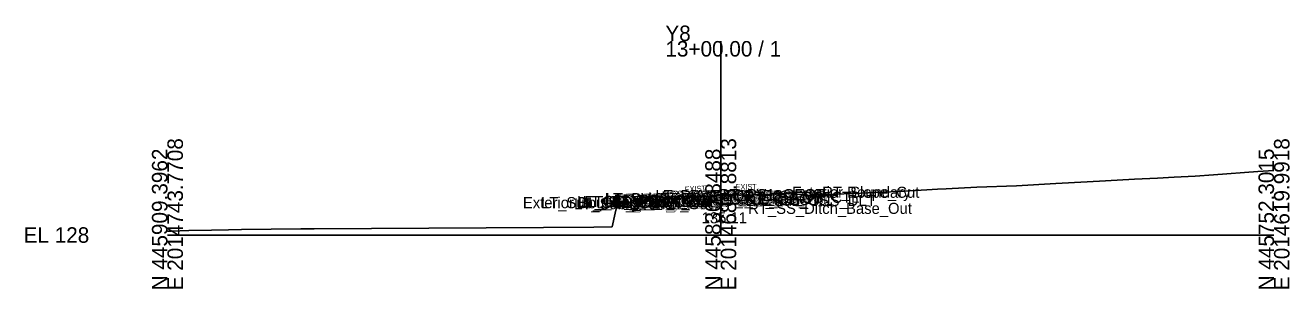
# Model space of a CAD drawing. Extents: x -26 to 1403, y -10 to 8043.
# Drawn here: x -25.7 to 202.8, y 5990.3 to 6037.9 of the extents above; entities that cross this region are included whole.
import ezdxf

# ---------------------------------------------------------------- set-up
doc = ezdxf.new("R2010")
doc.units = 0
for name, color, linetype in [('Default', 7, 'Continuous'), ('Exist Cross Section Cell', 7, 'Continuous'), ('Exist XS Center Line Elevation Label', 7, 'Continuous'), ('Exist XS Ground Line', 7, 'Continuous'), ('Prop CMT Shld Paved Course 1', 7, 'Continuous'), ('Prop XS SE Text', 7, 'Continuous'), ('Scratch_Level_0', 7, 'Continuous')]:
    doc.layers.add(name, color=color, linetype=linetype)

msp = doc.modelspace()

# ---------------------------------------------------------------- linework, layer by layer
at = {"layer": 'Exist Cross Section Cell'}
for p, q in [((100, 6000), (100, 6035.02)), ((0, 6000), (100, 6000)), ((100, 6000), (200, 6000))]:
    msp.add_line(p, q, dxfattribs=at)
at = {"layer": 'Exist XS Ground Line'}
msp.add_lwpolyline([(0, 6000.71), (0.68, 6000.72), (3.89, 6000.82), (7.97, 6000.89), (11.02, 6000.92), (13.41, 6000.98), (24.13, 6001.1), (25.26, 6001.11), (26.52, 6001.12), (67.99, 6001.36), (77.04, 6001.44), (80.37, 6001.49), (80.93, 6003.93), (81.37, 6005.77), (84.19, 6006), (85.79, 6006.13), (90.69, 6006.51), (96.04, 6006.83), (100, 6007.11), (100.96, 6007.18), (102.69, 6007.21), (108.94, 6007.31), (109.07, 6007.42), (111.89, 6007.46), (113.23, 6007.66), (115.29, 6007.66), (115.71, 6007.16), (116.35, 6007.2), (117.3, 6007.25), (123.96, 6007.52), (132.08, 6007.87), (137.25, 6008.14), (139.2, 6008.25), (140.74, 6008.32), (146.32, 6008.61), (153.47, 6008.89), (160.57, 6009.3), (166.21, 6009.61), (169.57, 6009.78), (174.81, 6010.06), (178.94, 6010.28), (181.93, 6010.44), (185.73, 6010.61), (189.05, 6010.84), (197.08, 6011.46), (200, 6011.67)], dxfattribs=at)
at = {"layer": 'Prop CMT Shld Paved Course 1'}
for points in [[(90.69, 6006.55), (90.69, 6006.55)], [(108.94, 6007.29), (108.94, 6007.29)]]:
    msp.add_lwpolyline(points, dxfattribs=at)

# ---------------------------------------------------------------- texts
at = {"layer": 'Default'}
msp.add_text('-', height=0.0001, dxfattribs=at).set_placement((0, 6000))
at = {"layer": 'Exist Cross Section Cell'}
for s, p in [('Y8', (90, 6035.02)), ('13+00.00 / 1', (90, 6032.22)), ('EL 128', (-26, 5998.6))]:
    msp.add_text(s, height=2.8, dxfattribs=at).set_placement(p)
for s, p in [('E 2014743.7708', (2.8, 5990)), ('E 2014681.8813', (102.8, 5990)), ('E 2014619.9918', (202.8, 5990)), ('N 445909.3962', (0, 5990)), ('N 445830.8488', (100, 5990)), ('N 445752.3015', (200, 5990))]:
    msp.add_text(s, height=2.8, rotation=90, dxfattribs=at).set_placement(p)
at = {"layer": 'Exist XS Center Line Elevation Label'}
msp.add_text('135.11', height=2, dxfattribs=at).set_placement((96.56, 6002.11))
at = {"layer": 'Prop XS SE Text'}
for rotation, p in [(3.4336, (93.52, 6007.72)), (1.1458, (102.68, 6008.16))]:
    msp.add_text('EXIST.', height=1, rotation=rotation, dxfattribs=at).set_placement(p)
at = {"layer": 'Scratch_Level_0'}
for s, p in [('LT_PV_IEEOP_EG', (88.19, 6006.11)), ('PV1_PGL', (94.47, 6006.11)), ('RT_PV1_OEOT', (99.63, 6006.29)), ('RT_PS1_OEOP', (99.69, 6006.29)), ('Exterior Boundary', (112.9, 6006.72)), ('RT_Slope_Cut', (118.35, 6006.72)), ('Exterior Boundary', (64.25, 6004.84)), ('LT_Sub_OSS_DLT', (67.51, 6004.84)), ('LT_Sub_Trench_Out', (73.5, 6004.65)), ('LT_GS_OS_CTL', (74.06, 6005.07)), ('LT_Slope_Fill', (75.09, 6005.03)), ('LT_PS3_Shelf_Out', (75.66, 6005.03)), ('LT_Sub Tie Out', (79.03, 6005.57)), ('LT_PV_OEEOP_EG', (79.23, 6005.57)), ('LT_PS3_OEOP', (80.41, 6005.04)), ('LT_PS2_OEOP', (80.67, 6005.3)), ('LT_Sub_OEOT', (80.77, 6004.68)), ('LT_PV2_OEOT', (80.86, 6005.3)), ('LT_PV3_OEOT', (80.86, 6005.05)), ('LT_Sub_OEEOP', (80.9, 6004.74)), ('LT_PV2_OEEOP', (80.99, 6005.36)), ('LT_PV3_OEEOP', (80.99, 6005.11)), ('LT_PV1_OEOT', (81.43, 6005.55)), ('LT_PS1_OEOP', (81.49, 6005.55)), ('LT_PV1_OEEOP', (81.56, 6005.49)), ('RT_Sub_OEEOP', (89.17, 6005.24)), ('RT_PV2_OEEOP', (89.26, 6005.86)), ('RT_PV3_OEEOP', (89.26, 6005.61)), ('RT_PV1_OEEOP', (89.83, 6005.99)), ('RT_PV2_IEEOP', (89.91, 6005.86)), ('LT_PV2_IEEOP', (89.95, 6005.86)), ('LT_PV3_IEEOP', (89.95, 6005.61)), ('RT_PV1_IEEOP', (90.47, 6005.99)), ('LT_PV1_IEEOP', (90.52, 6005.99)), ('PV2_PGL', (93.91, 6005.86)), ('RT_Sub_Trench_Out', (94.49, 6005.39)), ('RT_PS3_Shelf_Out', (95.88, 6005.77)), ('RT_Sub_OEOT', (98.97, 6005.41)), ('RT_PV2_OEOT', (99.06, 6006.04)), ('RT_PV3_OEOT', (99.06, 6005.79)), ('RT_PS2_OEOP', (99.38, 6006.03)), ('RT_PS3_OEOP', (99.64, 6005.78)), ('RT_GS_OS_CTL', (104.26, 6005.81)), ('RT_Sub_OSS_DLT', (104.53, 6005.25)), ('RT_SS_Ditch_Base_Out', (104.97, 6003.81))]:
    msp.add_text(s, height=2, dxfattribs=at).set_placement(p)

doc.saveas('drawing.dxf')
